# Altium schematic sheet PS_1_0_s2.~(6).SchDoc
size A4
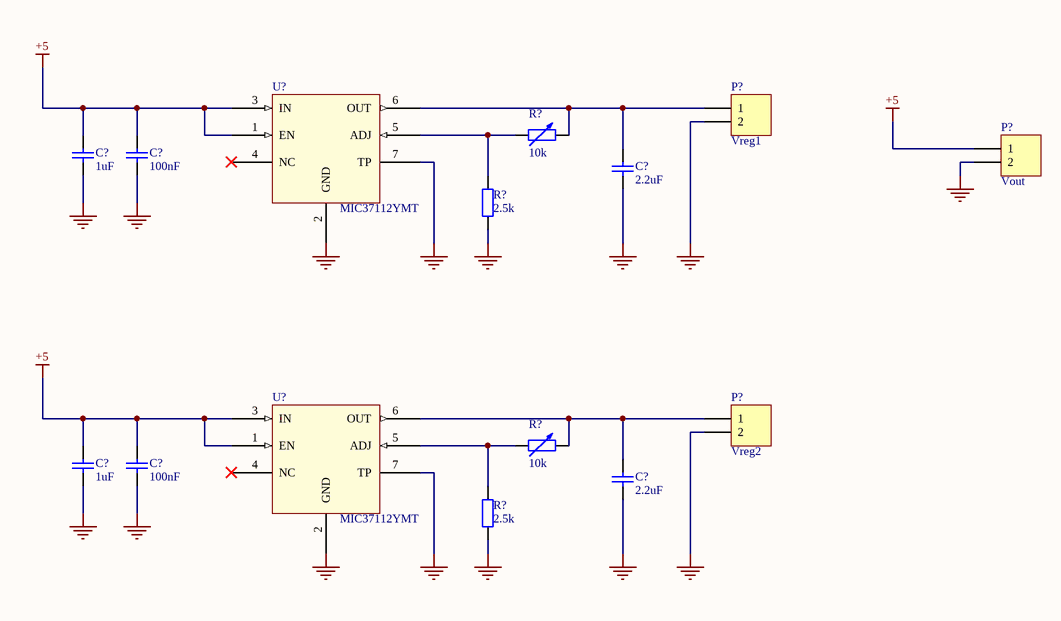
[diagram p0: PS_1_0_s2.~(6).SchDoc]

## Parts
(Parts that share a designator on the sheet are numbered #1, #2 ... from top to bottom, then left to right.)
C?#1  1uF  [0603]
C?#2  100nF  [0603]
C?#3  2.2uF  [0603]
C?#4  1uF  [0603]
C?#5  100nF  [0603]
C?#6  2.2uF  [0603]
P?#1  Vreg1  [HDR1X2]
P?#2  Vout  [HDR1X2]
P?#3  Vreg2  [HDR1X2]
R?#1  10k  [AXIAL-0.6]
R?#2  2.5k  [0603]
R?#3  10k  [AXIAL-0.6]
R?#4  2.5k  [0603]
U?#1  MIC37112YMT
U?#2  MIC37112YMT

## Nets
+5: C?#1.1 C?#2.1 C?#4.1 C?#5.1 P?#2.1 U?#1.1(EN) U?#1.3(IN) U?#2.1(EN) U?#2.3(IN)
GND: C?#1.2 C?#2.2 C?#3.2 C?#4.2 C?#5.2 C?#6.2 P?#1.2 P?#2.2 P?#3.2 R?#2.1 R?#4.1 U?#1.2(GND) U?#1.7(TP) U?#2.2(GND) U?#2.7(TP)
NetC?#3_1: C?#3.1 P?#1.1 R?#1.2 U?#1.6(OUT)
NetC?#6_1: C?#6.1 P?#3.1 R?#3.2 U?#2.6(OUT)
NetR?#1_1: R?#1.1 R?#2.2 U?#1.5(ADJ)
NetR?#3_1: R?#3.1 R?#4.2 U?#2.5(ADJ)

Not connected (* = marked no-connect by the designer): U?#1 4(NC)*; U?#2 4(NC)*

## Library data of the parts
C?#1-C?#6 = Cap Semi: Capacitor (Semiconductor SIM Model)
P?#1-P?#3 = Header 2: Header, 2-Pin
R?#1 R?#3 = Res Adj2: Variable Resistor; Set Position: 0.5
R?#2 R?#4 = Res2: Resistor
U?#1 U?#2 = MIC37112YMT: LDO, 1A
